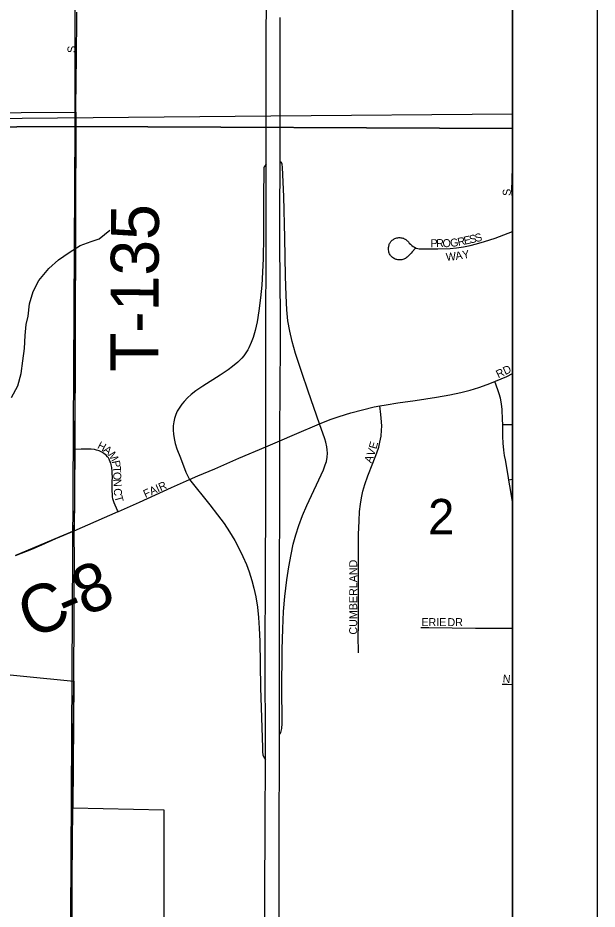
# Model space of a CAD drawing. Extents: x 0 to 1391, y -24 to 440.
# Drawn here: x 466.29 to 480, y 311.03 to 332.13 of the extents above; entities that cross this region are included whole.
import ezdxf

# ---------------------------------------------------------------- set-up
doc = ezdxf.new("R2010")
doc.units = 0
for name, color, linetype in [('GM_X_City_Street', 7, 'Continuous'), ('GM_X_City_Street_Text', 7, 'Continuous'), ('GM_X_Corporation', 7, 'Continuous'), ('GM_X_County_Road', 7, 'Continuous'), ('GM_X_County_Road_Text', 7, 'Continuous'), ('GM_X_Interchange_Ramps', 7, 'Continuous'), ('GM_X_Interstate_Route', 7, 'Continuous'), ('GM_X_Minor_River', 7, 'Continuous'), ('GM_X_Rail_Line', 7, 'Continuous'), ('GM_X_Section', 7, 'Continuous'), ('GM_X_Section_Text', 7, 'Continuous'), ('GM_X_Township', 7, 'Continuous'), ('GM_X_Township_Road', 7, 'Continuous'), ('GM_X_Township_Road_Text', 7, 'Continuous'), ('SH_Data', 7, 'Continuous')]:
    doc.layers.add(name, color=color, linetype=linetype)

msp = doc.modelspace()

# ---------------------------------------------------------------- linework, layer by layer
at = {"layer": 'GM_X_City_Street'}
for points in [[(467.663, 329.897), (467.672, 330.736), (467.675, 331.091), (467.688, 332.246), (467.688, 332.258)], [(478, 327.856), (477.997, 327.875), (477.981, 328.051), (477.986, 328.298), (478, 328.597)], [(475.699, 326.678), (475.622, 326.586), (475.597, 326.559), (475.572, 326.534), (475.557, 326.517), (475.539, 326.497), (475.517, 326.475), (475.5, 326.459), (475.482, 326.444), (475.463, 326.431), (475.443, 326.42), (475.421, 326.411), (475.399, 326.403), (475.374, 326.399), (475.346, 326.396), (475.323, 326.396), (475.305, 326.397), (475.284, 326.399), (475.262, 326.404), (475.241, 326.41), (475.22, 326.418), (475.196, 326.43), (475.177, 326.442), (475.158, 326.454), (475.142, 326.468), (475.125, 326.484), (475.109, 326.502), (475.098, 326.52), (475.087, 326.539), (475.079, 326.56), (475.072, 326.583), (475.067, 326.607), (475.063, 326.633), (475.061, 326.662), (475.063, 326.69), (475.066, 326.711), (475.07, 326.729), (475.075, 326.747), (475.081, 326.766), (475.089, 326.785), (475.098, 326.8), (475.106, 326.815), (475.117, 326.83), (475.134, 326.847), (475.152, 326.863), (475.181, 326.884), (475.197, 326.895), (475.215, 326.903), (475.235, 326.911), (475.257, 326.917), (475.282, 326.921), (475.306, 326.924), (475.328, 326.924), (475.351, 326.923), (475.376, 326.919), (475.398, 326.915), (475.416, 326.908), (475.436, 326.899), (475.454, 326.888), (475.469, 326.879), (475.487, 326.866), (475.503, 326.852), (475.517, 326.838), (475.532, 326.822), (475.555, 326.795), (475.579, 326.769), (475.612, 326.74), (475.643, 326.717), (475.678, 326.695), (475.719, 326.677), (475.758, 326.667), (475.788, 326.661), (475.807, 326.658), (475.966, 326.658), (476.23, 326.66), (476.52, 326.67), (476.668, 326.683), (476.837, 326.706), (476.998, 326.742), (477.141, 326.778), (477.33, 326.83), (477.587, 326.915), (478, 327.07)], [(477.58, 323.518), (477.597, 323.524), (477.86, 323.64), (478, 323.707)], [(474.859, 322.943), (475.004, 322.971), (475.284, 323.017), (475.69, 323.073), (476.195, 323.151), (476.514, 323.207), (476.772, 323.26), (476.992, 323.315), (477.196, 323.376), (477.399, 323.445), (477.58, 323.518)], [(477.768, 322.499), (477.763, 322.618), (477.749, 322.853), (477.734, 322.989), (477.711, 323.123), (477.682, 323.231), (477.649, 323.325), (477.58, 323.518)], [(473.433, 322.518), (473.683, 322.618), (473.892, 322.692), (474.173, 322.78), (474.448, 322.851), (474.725, 322.916), (474.859, 322.943)], [(474.35, 317.094), (474.346, 317.504), (474.349, 317.715), (474.351, 318.124), (474.353, 318.509), (474.35, 318.77), (474.351, 319.031), (474.352, 319.341), (474.356, 319.589), (474.353, 319.9), (474.366, 320.223), (474.379, 320.446), (474.398, 320.618), (474.422, 320.765), (474.457, 320.923), (474.502, 321.078), (474.574, 321.289), (474.693, 321.59), (474.789, 321.832), (474.831, 321.962), (474.86, 322.083), (474.885, 322.229), (474.9, 322.365), (474.904, 322.464), (474.9, 322.564), (474.881, 322.736), (474.859, 322.943)], [(470.35, 321.196), (470.553, 321.283), (470.952, 321.456), (471.522, 321.702), (472.157, 321.974), (472.492, 322.117), (472.836, 322.265), (473.433, 322.518)], [(477.768, 322.499), (477.814, 322.499), (478, 322.499)], [(477.91, 321.184), (477.892, 321.297), (477.828, 321.665), (477.81, 321.767), (477.791, 321.898), (477.775, 322.059), (477.769, 322.22), (477.769, 322.468), (477.768, 322.499)], [(468.661, 320.443), (468.651, 320.468), (468.57, 320.65), (468.551, 320.698), (468.541, 320.741), (468.532, 320.79), (468.527, 320.838), (468.522, 320.939), (468.525, 321.124), (468.524, 321.147), (468.527, 321.266), (468.524, 321.33), (468.521, 321.393), (468.512, 321.485), (468.502, 321.543), (468.488, 321.591), (468.471, 321.635), (468.45, 321.679), (468.433, 321.71), (468.412, 321.735), (468.378, 321.772), (468.329, 321.815), (468.275, 321.849), (468.216, 321.877), (468.155, 321.897), (468.105, 321.908), (468.029, 321.915), (467.915, 321.917), (467.786, 321.914), (467.643, 321.911)], [(468.661, 320.443), (468.669, 320.446), (469.17, 320.666), (469.928, 321.009), (470.35, 321.196)], [(478, 321.2), (477.946, 321.191), (477.91, 321.184)], [(478, 320.675), (477.953, 320.917), (477.91, 321.184)], [(467.623, 319.983), (468.661, 320.443)], [(467.613, 316.43), (467.623, 318.042), (467.627, 318.701), (467.629, 319.223), (467.623, 319.983)], [(475.825, 317.699), (476.017, 317.698), (477.121, 317.683), (477.568, 317.684), (477.828, 317.684), (478, 317.683)], [(477.748, 316.357), (477.874, 316.355), (477.982, 316.35), (478, 316.349)]]:
    msp.add_lwpolyline(points, dxfattribs=at)
at = {"layer": 'GM_X_Corporation'}
msp.add_line((478, 308.53), (478, 378.802), dxfattribs=at)
for points in [[(452.126, 329.802), (467.663, 329.897), (467.643, 321.906), (467.623, 319.983), (467.379, 319.881), (466.238, 319.399)], [(457.213, 310.17), (458.302, 311.223), (459.499, 312.7), (461.564, 312.583), (462.013, 313.628), (462.893, 315.766), (462.369, 315.765), (462.565, 316.267), (463.154, 316.856), (463.046, 316.932), (462.806, 318.059), (463.977, 318.079), (464.207, 318.462), (464.712, 318.195), (464.192, 317.695), (464.193, 316.766), (467.613, 316.43), (467.59, 313.428), (469.744, 313.385), (469.744, 309.635)]]:
    msp.add_lwpolyline(points, dxfattribs=at)
at = {"layer": 'GM_X_County_Road'}
msp.add_lwpolyline([(466.238, 319.399), (466.618, 319.554), (466.858, 319.656), (467.187, 319.8), (467.623, 319.983)], dxfattribs=at)
at = {"layer": 'GM_X_Interchange_Ramps'}
for points in [[(473.433, 322.518), (473.297, 322.901), (473.16, 323.287), (473.009, 323.734), (472.865, 324.184), (472.781, 324.47), (472.724, 324.711), (472.683, 324.956), (472.656, 325.216), (472.637, 325.551), (472.625, 326.01), (472.608, 326.917), (472.589, 327.898), (472.557, 328.585), (472.546, 328.66), (472.537, 328.687), (472.52, 328.707), (472.499, 328.721), (472.497, 328.72)], [(472.165, 328.669), (472.142, 328.635), (472.121, 328.599), (472.115, 328.58), (472.112, 328.558), (472.112, 328.487), (472.105, 327.933), (472.102, 326.952), (472.093, 326.43), (472.083, 326.107), (472.064, 325.797), (472.035, 325.5), (471.995, 325.192), (471.951, 324.935), (471.906, 324.728), (471.858, 324.56), (471.816, 324.444), (471.76, 324.319), (471.731, 324.265), (471.642, 324.13), (471.593, 324.074), (471.499, 323.976), (471.374, 323.873), (471.264, 323.792), (471.077, 323.669), (470.668, 323.409), (470.504, 323.296), (470.395, 323.212), (470.302, 323.13), (470.224, 323.049), (470.169, 322.983), (470.105, 322.891), (470.063, 322.815), (470.028, 322.735), (469.998, 322.641), (469.981, 322.568), (469.969, 322.47), (469.966, 322.37), (469.972, 322.271), (469.987, 322.173), (470.015, 322.052), (470.057, 321.922), (470.137, 321.713), (470.268, 321.377), (470.35, 321.196)], [(472.479, 315.165), (472.5, 315.19), (472.512, 315.213), (472.523, 315.243), (472.535, 315.303), (472.544, 315.422), (472.546, 315.564), (472.534, 316.173), (472.545, 317.179), (472.558, 317.664), (472.579, 318.073), (472.609, 318.433), (472.655, 318.828), (472.7, 319.135), (472.756, 319.428), (472.81, 319.671), (472.867, 319.887), (472.938, 320.112), (473.025, 320.345), (473.126, 320.585), (473.236, 320.822), (473.413, 321.192), (473.521, 321.429), (473.567, 321.545), (473.593, 321.627), (473.609, 321.725), (473.616, 321.825), (473.614, 321.899), (473.604, 321.973), (473.579, 322.082), (473.557, 322.166), (473.433, 322.518)], [(470.35, 321.196), (470.833, 320.601), (471.016, 320.366), (471.17, 320.155), (471.302, 319.96), (471.424, 319.757), (471.53, 319.56), (471.616, 319.381), (471.699, 319.187), (471.763, 319.012), (471.827, 318.811), (471.876, 318.63), (471.922, 318.424), (471.962, 318.179), (471.988, 317.932), (472.005, 317.684), (472.016, 317.373), (472.034, 316.279), (472.083, 314.849), (472.082, 314.757), (472.092, 314.681), (472.11, 314.624), (472.148, 314.561)]]:
    msp.add_lwpolyline(points, dxfattribs=at)
at = {"layer": 'GM_X_Interstate_Route'}
for points in [[(472.134, 310.207), (472.138, 311.151), (472.147, 313.239), (472.148, 314.42), (472.148, 314.561), (472.147, 317.265), (472.155, 318.732), (472.156, 320.919), (472.157, 321.974), (472.162, 323.641), (472.163, 325.144), (472.167, 326.263), (472.165, 328.388), (472.165, 328.669), (472.166, 329.022), (472.169, 329.556), (472.17, 330.414), (472.169, 331.01), (472.17, 331.818), (472.183, 332.924)], [(472.501, 330.282), (472.502, 330.582), (472.501, 331.638), (472.502, 332.135)], [(472.499, 329.681), (472.501, 330.282)], [(472.492, 321.903), (472.492, 322.117), (472.501, 323.537), (472.506, 324.232), (472.503, 325.052), (472.491, 326.767), (472.491, 327.003), (472.494, 327.513), (472.497, 328.656), (472.497, 328.72), (472.498, 329.426), (472.499, 329.681)], [(472.48, 316.644), (472.482, 318.243), (472.491, 321.35), (472.492, 321.903)], [(472.474, 309.291), (472.477, 312.452), (472.479, 315.165), (472.479, 315.72), (472.48, 316.644)]]:
    msp.add_lwpolyline(points, dxfattribs=at)
at = {"layer": 'GM_X_Minor_River'}
msp.add_lwpolyline([(466.144, 323.142), (466.292, 323.42), (466.371, 323.707), (466.406, 324.01), (466.448, 324.297), (466.467, 324.607), (466.485, 324.872), (466.534, 325.068), (466.568, 325.356), (466.655, 325.65), (466.788, 325.906), (467.027, 326.19), (467.25, 326.399), (467.504, 326.569), (467.764, 326.739), (468.024, 326.834), (468.215, 326.899), (468.469, 327.1)], dxfattribs=at)
at = {"layer": 'GM_X_Rail_Line'}
msp.add_lwpolyline([(447.033, 329.567), (472.279, 329.809), (478, 329.856)], dxfattribs=at)
at = {"layer": 'GM_X_Section'}
for p, q in [((478, 329.504), (478, 349.585)), ((478, 309.371), (478, 329.504))]:
    msp.add_line(p, q, dxfattribs=at)
for points in [[(467.652, 349.609), (467.641, 329.557), (447.102, 329.433), (447.184, 349.582)], [(467.641, 329.557), (467.529, 309.386), (447.244, 309.439), (447.102, 329.433)]]:
    msp.add_lwpolyline(points, close=True, dxfattribs=at)
for points in [[(478, 349.585), (467.652, 349.609), (467.641, 329.557), (478, 329.504)], [(478, 329.504), (467.641, 329.557), (467.529, 309.386), (478, 309.371)]]:
    msp.add_lwpolyline(points, dxfattribs=at)
at = {"layer": 'GM_X_Township'}
msp.add_lwpolyline([(478, 305.116), (478, 388.948)], dxfattribs=at)
at = {"layer": 'GM_X_Township_Road'}
for points in [[(467.643, 321.911), (467.643, 322.293), (467.648, 322.898), (467.649, 323.635), (467.647, 324.312), (467.656, 325.399), (467.659, 326.421), (467.661, 327.317), (467.664, 328.513), (467.664, 329.067), (467.663, 329.897)], [(467.623, 319.983), (467.638, 320.541), (467.641, 320.927), (467.642, 321.583), (467.643, 321.911)], [(467.59, 313.428), (467.587, 313.711), (467.6, 315.092), (467.613, 316.43)], [(467.474, 299.39), (467.486, 301.107), (467.501, 302.486), (467.51, 303.443), (467.52, 304.077), (467.52, 304.686), (467.523, 305.283), (467.528, 305.967), (467.533, 306.824), (467.542, 307.781), (467.544, 308.527), (467.556, 309.384), (467.565, 310.404), (467.575, 311.124), (467.579, 311.783), (467.59, 313.428)]]:
    msp.add_lwpolyline(points, dxfattribs=at)
at = {"layer": 'SH_Data'}
for p, q in [((480, 420), (480, 280)), ((478, 418), (478, 282))]:
    msp.add_line(p, q, dxfattribs=at)

# ---------------------------------------------------------------- texts
at = {"layer": 'GM_X_City_Street_Text'}
for s, height, rotation, p in [('S', 0.189, 90, (467.655, 331.296)), ('S', 0.189, 90, (477.955, 327.913)), ('S', 0.189, 14.5936, (477.131, 326.815)), ('P', 0.189, 0.1639, (476.057, 326.698)), ('R', 0.189, 0.17, (476.19, 326.699)), ('O', 0.189, 0.3079, (476.341, 326.699)), ('G', 0.189, 7.0622, (476.532, 326.702)), ('R', 0.189, 11.9643, (476.715, 326.725)), ('E', 0.189, 12.1755, (476.862, 326.756)), ('S', 0.189, 12.6428, (476.994, 326.785)), ('W', 0.189, 5.2355, (476.428, 326.373)), ('A', 0.189, 9.4074, (476.659, 326.394)), ('Y', 0.189, 10.0609, (476.826, 326.422)), ('RD', 0.1894, 25.2073, (477.659, 323.593)), ('H', 0.189, 332.1834, (468.155, 321.945)), ('A', 0.189, 323.4842, (468.296, 321.871)), ('V', 0.189, 71.5074, (474.717, 321.738)), ('E', 0.189, 74.8936, (474.774, 321.908)), ('M', 0.189, 300.9513, (468.417, 321.787)), ('A', 0.189, 69.5949, (474.657, 321.575)), ('P', 0.189, 281.8296, (468.514, 321.631)), ('T', 0.189, 272.8692, (468.54, 321.508)), ('O', 0.189, 271.7271, (468.547, 321.376)), ('N', 0.189, 271.7271, (468.552, 321.209)), ('FAIR', 0.1894, 24.1468, (469.31, 320.76)), ('C', 0.189, 273.6158, (468.559, 320.986)), ('T', 0.189, 285.1533, (468.575, 320.795)), ('CUMBERLAND', 0.1894, 90, (474.321, 317.529)), ('ERIE', 0.1894, 0, (475.84, 317.729)), ('DR', 0.1894, 0, (476.457, 317.729)), ('N', 0.189, 355.318, (477.759, 316.398))]:
    msp.add_text(s, height=height, rotation=rotation, dxfattribs=at).set_placement(p)
at = {"layer": 'GM_X_County_Road_Text'}
for s, rotation, p in [('8', 22.8313, (467.88, 317.956)), ('C', 22.9111, (466.601, 317.415)), ('-', 22.8956, (467.455, 317.776))]:
    msp.add_text(s, height=1.136, rotation=rotation, dxfattribs=at).set_placement(p)
at = {"layer": 'GM_X_Section_Text'}
msp.add_text('2', height=0.837, rotation=0, dxfattribs=at).set_placement((475.999, 319.903))
at = {"layer": 'GM_X_Township_Road_Text'}
msp.add_text('T-135', height=1.1364, rotation=89.7209, dxfattribs=at).set_placement((469.613, 323.744))

doc.saveas('drawing.dxf')
